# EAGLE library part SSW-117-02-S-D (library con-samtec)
THROUGH-HOLE .025" SQ POST SOCKET Source: Samtec SSW.pdf
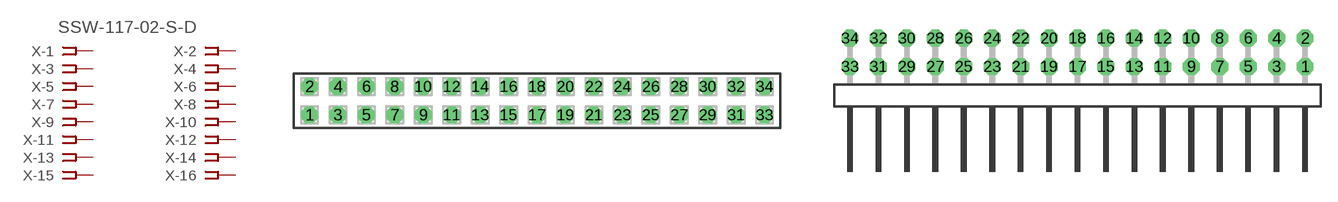
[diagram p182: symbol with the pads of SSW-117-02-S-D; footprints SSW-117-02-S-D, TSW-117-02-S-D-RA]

Designator prefix X; gates -1=FPINV -2=FPIN -3=FPIN -4=FPIN -5=FPIN -6=FPIN -7=FPIN -8=FPIN -9=FPIN -10=FPIN -11=FPIN -12=FPIN -13=FPIN -14=FPIN -15=FPIN -16=FPIN -17=FPIN -18=FPIN -19=FPIN -20=FPIN -21=FPIN -22=FPIN -23=FPIN -24=FPIN -25=FPIN -26=FPIN -27=FPIN -28=FPIN -29=FPIN -30=FPIN -31=FPIN -32=FPIN -33=FPIN -34=FPIN

## SSW-117-02-S-D (MPN: SSW-117-02-S-D; OC_FARNELL: unknown; OC_NEWARK: 11P9590)  [SSW-117-02-S-D]
1  -1:1  pas
2  -2:1  pas
3  -3:1  pas
4  -4:1  pas
5  -5:1  pas
6  -6:1  pas
7  -7:1  pas
8  -8:1  pas
9  -9:1  pas
10  -10:1  pas
11  -11:1  pas
12  -12:1  pas
13  -13:1  pas
14  -14:1  pas
15  -15:1  pas
16  -16:1  pas
17  -17:1  pas
18  -18:1  pas
19  -19:1  pas
20  -20:1  pas
21  -21:1  pas
22  -22:1  pas
23  -23:1  pas
24  -24:1  pas
25  -25:1  pas
26  -26:1  pas
27  -27:1  pas
28  -28:1  pas
29  -29:1  pas
30  -30:1  pas
31  -31:1  pas
32  -32:1  pas
33  -33:1  pas
34  -34:1  pas

## SSW-117-02-S-D-RA (MPN: SSW-117-02-S-D-RA; OC_FARNELL: unknown; OC_NEWARK: 11P9591)  [TSW-117-02-S-D-RA]
Pads as for SSW-117-02-S-D

## Footprint SSW-117-02-S-D (pad centres in mm)
THROUGH-HOLE .025" SQ POST SOCKET Source: Samtec SSW.pdf
drill 1 pad 1.5 octagon: 1 -20.32,-1.27; 2 -20.32,1.27; 3 -17.78,-1.27; 4 -17.78,1.27; 5 -15.24,-1.27; 6 -15.24,1.27; 7 -12.7,-1.27; 8 -12.7,1.27; 9 -10.16,-1.27; 10 -10.16,1.27; 11 -7.62,-1.27; 12 -7.62,1.27; 13 -5.08,-1.27; 14 -5.08,1.27; 15 -2.54,-1.27; 16 -2.54,1.27; 17 0,-1.27; 18 0,1.27; 19 2.54,-1.27; 20 2.54,1.27; 21 5.08,-1.27; 22 5.08,1.27; 23 7.62,-1.27; 24 7.62,1.27; 25 10.16,-1.27; 26 10.16,1.27; 27 12.7,-1.27; 28 12.7,1.27; 29 15.24,-1.27; 30 15.24,1.27; 31 17.78,-1.27; 32 17.78,1.27; 33 20.32,-1.27; 34 20.32,1.27

## Footprint TSW-117-02-S-D-RA (pad centres in mm)
THROUGH-HOLE .025" SQ POST HEADER Source: Samtec TSW.pdf
drill 1 pad 1.5 octagon: 1 20.32,1.524; 2 20.32,4.064; 3 17.78,1.524; 4 17.78,4.064; 5 15.24,1.524; 6 15.24,4.064; 7 12.7,1.524; 8 12.7,4.064; 9 10.16,1.524; 10 10.16,4.064; 11 7.62,1.524; 12 7.62,4.064; 13 5.08,1.524; 14 5.08,4.064; 15 2.54,1.524; 16 2.54,4.064; 17 0,1.524; 18 0,4.064; 19 -2.54,1.524; 20 -2.54,4.064; 21 -5.08,1.524; 22 -5.08,4.064; 23 -7.62,1.524; 24 -7.62,4.064; 25 -10.16,1.524; 26 -10.16,4.064; 27 -12.7,1.524; 28 -12.7,4.064; 29 -15.24,1.524; 30 -15.24,4.064; 31 -17.78,1.524; 32 -17.78,4.064; 33 -20.32,1.524; 34 -20.32,4.064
